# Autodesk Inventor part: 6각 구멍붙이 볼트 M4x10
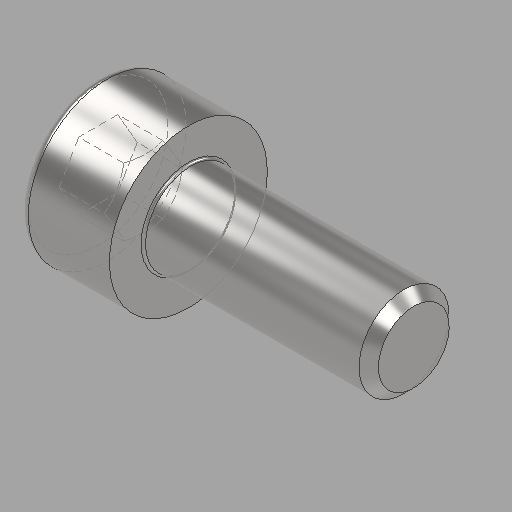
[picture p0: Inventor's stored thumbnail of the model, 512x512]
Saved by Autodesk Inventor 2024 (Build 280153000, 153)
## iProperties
Created: 2025-11
Part Number: 6각 구멍붙이 볼트 M4x10
Material: 강철, 연강
Description: 6각머리 태핑 나사
Document SubType Name: Modeling
Designer: Edu09
Density: 7.85 g/cm^3
Appearance: 기본값
Author: jhkim
Sending System: Autodesk Inventor 2026
Preprocessor: ST-DEVELOPER v20.1
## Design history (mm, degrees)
feature "Solid1"
node "솔리드1"
